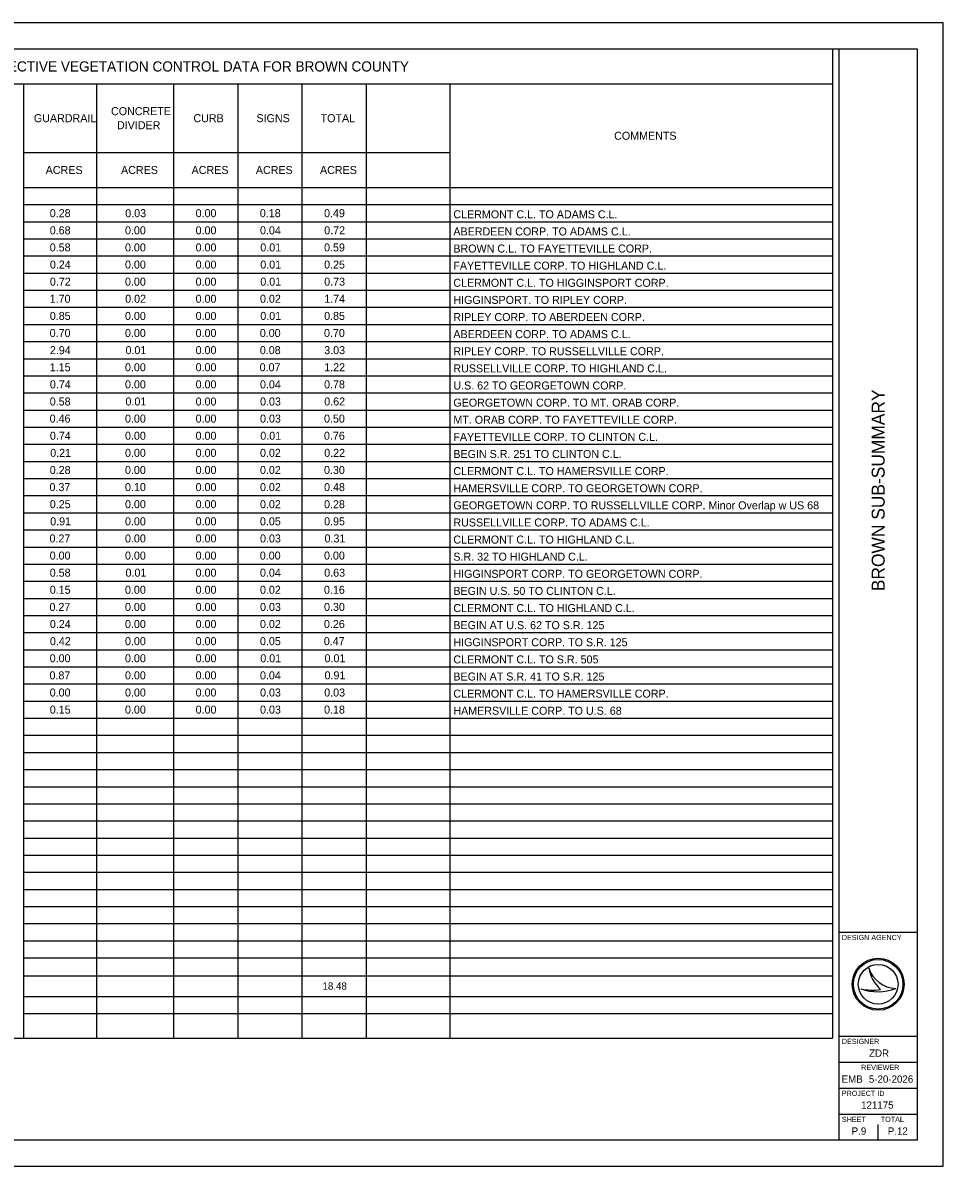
# Model space of a CAD drawing. Extents: x 0 to 34, y 0 to 22.
# Drawn here: x 16.29 to 34, y 0 to 22 of the extents above; entities that cross this region are included whole.
import ezdxf

# ---------------------------------------------------------------- set-up
doc = ezdxf.new("R2010")
doc.units = 0
for name, color, linetype in [('SH_Border', 7, 'Continuous'), ('SH_Cut_Line', 7, 'Continuous'), ('SH_Data', 7, 'Continuous'), ('SH_Text', 7, 'Continuous')]:
    doc.layers.add(name, color=color, linetype=linetype)

msp = doc.modelspace()

# ---------------------------------------------------------------- linework, layer by layer
at = {"layer": 'SH_Border'}
for p, q in [((32, 0.5), (32, 21.5)), ((32, 4.5), (33.5, 4.5)), ((32, 2.5), (33.5, 2.5)), ((32, 2), (33.5, 2)), ((32, 1.5), (33.5, 1.5)), ((32, 1), (33.5, 1))]:
    msp.add_line(p, q, dxfattribs=at)
msp.add_lwpolyline([(1.5, 21.5), (33.5, 21.5), (33.5, 0.5), (1.5, 0.5)], close=True, dxfattribs=at)
at = {"layer": 'SH_Cut_Line'}
msp.add_lwpolyline([(0, 0), (34, 0), (34, 22), (0, 22)], close=True, dxfattribs=at)
at = {"layer": 'SH_Data'}
for p, q in [((32.567, 3.81), (32.567, 3.81)), ((32.417, 3.41), (32.417, 3.41)), ((32.75, 3.5), (32.75, 3.5)), ((33.087, 3.419), (33.087, 3.419)), ((32.375, 0.675), (32.375, 0.675)), ((32.75, 0.5), (32.75, 0.8))]:
    msp.add_line(p, q, dxfattribs=at)
for radius in [0.5, 0.477, 0.477, 0.382]:
    msp.add_circle((32.75, 3.5), radius, dxfattribs=at)
for centre, radius, start, end in [((33.116, 3.998), 0.58, 198.9257, 198.9319), ((33.347, 3.97), 0.796, 191.6379, 191.6421), ((33.116, 3.998), 0.58, 198.9319, 267.1657), ((33.347, 3.97), 0.796, 191.6421, 226.0947), ((32.739, 4.37), 1.013, 251.4576, 290.0832), ((32.648, 4.654), 1.266, 259.4964, 259.4995), ((32.739, 4.37), 1.013, 251.4527, 251.4576), ((32.648, 4.654), 1.266, 259.4995, 276.6672)]:
    msp.add_arc(centre, radius, start, end, dxfattribs=at)
at = {"layer": 'SH_Text'}
for p, q in [((1.5, 21.5), (31.872, 21.5)), ((31.872, 21.5), (31.872, 2.46)), ((7.451, 20.825), (16.302, 20.825)), ((16.28, 20.825), (31.872, 20.825)), ((16.302, 20.825), (16.302, 2.46)), ((17.707, 20.825), (17.707, 2.46)), ((19.189, 20.825), (19.189, 2.46)), ((20.425, 20.825), (20.425, 2.46)), ((21.66, 20.825), (21.66, 2.46)), ((22.895, 20.825), (22.895, 2.46)), ((24.509, 20.825), (24.509, 2.46)), ((16.302, 19.507), (24.509, 19.507)), ((16.302, 18.832), (31.872, 18.832)), ((16.302, 18.502), (31.872, 18.502)), ((16.302, 18.173), (31.872, 18.173)), ((16.302, 17.844), (31.872, 17.844)), ((16.302, 17.514), (31.872, 17.514)), ((16.302, 17.185), (31.872, 17.185)), ((16.302, 16.855), (31.872, 16.855)), ((16.302, 16.526), (31.872, 16.526)), ((16.302, 16.196), (31.872, 16.196)), ((16.302, 15.867), (31.872, 15.867)), ((16.302, 15.538), (31.872, 15.538)), ((16.302, 15.208), (31.872, 15.208)), ((16.302, 14.879), (31.872, 14.879)), ((16.302, 14.549), (31.872, 14.549)), ((16.302, 14.22), (31.872, 14.22)), ((16.302, 13.891), (31.872, 13.891)), ((16.302, 13.561), (31.872, 13.561)), ((16.302, 13.232), (31.872, 13.232)), ((16.302, 12.902), (31.872, 12.902)), ((16.302, 12.573), (31.872, 12.573)), ((16.302, 12.244), (31.872, 12.244)), ((16.302, 11.914), (31.872, 11.914)), ((16.302, 11.585), (31.872, 11.585)), ((16.302, 11.255), (31.872, 11.255)), ((16.302, 10.926), (31.872, 10.926)), ((16.302, 10.596), (31.872, 10.596)), ((16.302, 10.267), (31.872, 10.267)), ((16.302, 9.938), (31.872, 9.938)), ((16.302, 9.608), (31.872, 9.608)), ((16.302, 9.279), (31.872, 9.279)), ((16.302, 8.949), (31.872, 8.949)), ((16.302, 8.62), (31.872, 8.62)), ((16.302, 8.291), (31.872, 8.291)), ((16.302, 7.961), (31.872, 7.961)), ((16.302, 7.632), (31.872, 7.632)), ((16.302, 7.302), (31.872, 7.302)), ((16.302, 6.973), (31.872, 6.973)), ((16.302, 6.644), (31.872, 6.644)), ((16.302, 6.314), (31.872, 6.314)), ((16.302, 5.985), (31.872, 5.985)), ((16.302, 5.655), (31.872, 5.655)), ((16.302, 5.326), (31.872, 5.326)), ((16.302, 4.996), (31.872, 4.996)), ((16.302, 4.667), (31.872, 4.667)), ((16.302, 4.338), (31.872, 4.338)), ((16.302, 4.008), (31.872, 4.008)), ((16.302, 3.662), (31.872, 3.662)), ((16.302, 3.267), (31.872, 3.267)), ((16.302, 2.938), (31.872, 2.938)), ((7.451, 2.46), (16.302, 2.46)), ((16.28, 2.46), (31.872, 2.46))]:
    msp.add_line(p, q, dxfattribs=at)

# ---------------------------------------------------------------- texts
at = {"layer": 'SH_Data'}
msp.add_text('BROWN SUB-SUMMARY', height=0.25, rotation=90, dxfattribs=at).set_placement((32.875, 11.064))
for s, height, p in [('DESIGN AGENCY', 0.1, (32.05, 4.35)), ('DESIGNER', 0.1, (32.05, 2.35)), ('ZDR', 0.14, (32.575, 2.105)), ('REVIEWER', 0.1, (32.422, 1.85)), ('EMB', 0.14, (32.047, 1.605)), ('5-20-2026', 0.14, (32.571, 1.605)), ('PROJECT ID', 0.1, (32.05, 1.35)), ('121175', 0.14, (32.421, 1.105)), ('SHEET', 0.1, (32.05, 0.85)), ('TOTAL', 0.1, (32.8, 0.85)), ('P.9', 0.14, (32.24, 0.605)), ('P.12', 0.14, (32.935, 0.605))]:
    msp.add_text(s, height=height, dxfattribs=at).set_placement(p)
at = {"layer": 'SH_Text'}
for s, height, p in [('HERBICIDAL SPRAYING NONSELECTIVE VEGETATION CONTROL DATA FOR BROWN COUNTY', 0.196, (11.852, 21.064)), ('GUARDRAIL', 0.154, (16.503, 20.089)), ('CONCRETE', 0.154, (17.987, 20.224)), ('CURB', 0.154, (19.573, 20.089)), ('SIGNS', 0.154, (20.786, 20.089)), ('TOTAL', 0.154, (22.02, 20.089)), ('DIVIDER', 0.154, (18.102, 19.954)), ('COMMENTS', 0.154, (27.669, 19.751)), ('ACRES', 0.154, (16.73, 19.092)), ('ACRES', 0.154, (18.18, 19.092)), ('ACRES', 0.154, (19.538, 19.092)), ('ACRES', 0.154, (20.774, 19.092)), ('ACRES', 0.154, (22.009, 19.092)), ('0.28', 0.154, (16.808, 18.261)), ('0.03', 0.154, (18.261, 18.261)), ('0.00', 0.154, (19.615, 18.261)), ('0.18', 0.154, (20.851, 18.261)), ('0.49', 0.154, (22.087, 18.261)), ('CLERMONT C.L. TO ADAMS C.L.', 0.154, (24.575, 18.239)), ('0.68', 0.154, (16.808, 17.931)), ('0.00', 0.154, (18.256, 17.931)), ('0.00', 0.154, (19.615, 17.931)), ('0.04', 0.154, (20.854, 17.931)), ('0.72', 0.154, (22.09, 17.931)), ('ABERDEEN CORP. TO ADAMS C.L.', 0.154, (24.575, 17.909)), ('0.58', 0.154, (16.808, 17.602)), ('0.00', 0.154, (18.256, 17.602)), ('0.00', 0.154, (19.615, 17.602)), ('0.01', 0.154, (20.86, 17.602)), ('0.59', 0.154, (22.087, 17.602)), ('BROWN C.L. TO FAYETTEVILLE CORP.', 0.154, (24.575, 17.58)), ('0.24', 0.154, (16.811, 17.272)), ('0.00', 0.154, (18.256, 17.272)), ('0.00', 0.154, (19.615, 17.272)), ('0.01', 0.154, (20.86, 17.272)), ('0.25', 0.154, (22.088, 17.272)), ('FAYETTEVILLE CORP. TO HIGHLAND C.L.', 0.154, (24.575, 17.251)), ('0.72', 0.154, (16.811, 16.943)), ('0.00', 0.154, (18.256, 16.943)), ('0.00', 0.154, (19.615, 16.943)), ('0.01', 0.154, (20.86, 16.943)), ('0.73', 0.154, (22.09, 16.943)), ('CLERMONT C.L. TO HIGGINSPORT CORP.', 0.154, (24.575, 16.921)), ('1.70', 0.154, (16.807, 16.614)), ('0.02', 0.154, (18.26, 16.614)), ('0.00', 0.154, (19.615, 16.614)), ('0.02', 0.154, (20.854, 16.614)), ('1.74', 0.154, (22.09, 16.614)), ('HIGGINSPORT. TO RIPLEY CORP.', 0.154, (24.575, 16.592)), ('0.85', 0.154, (16.809, 16.284)), ('0.00', 0.154, (18.256, 16.284)), ('0.00', 0.154, (19.615, 16.284)), ('0.01', 0.154, (20.86, 16.284)), ('0.85', 0.154, (22.088, 16.284)), ('RIPLEY CORP. TO ABERDEEN CORP.', 0.154, (24.575, 16.262)), ('0.70', 0.154, (16.807, 15.955)), ('0.00', 0.154, (18.256, 15.955)), ('0.00', 0.154, (19.615, 15.955)), ('0.00', 0.154, (20.85, 15.955)), ('0.70', 0.154, (22.086, 15.955)), ('ABERDEEN CORP. TO ADAMS C.L.', 0.154, (24.575, 15.933)), ('2.94', 0.154, (16.811, 15.625)), ('0.01', 0.154, (18.266, 15.625)), ('0.00', 0.154, (19.615, 15.625)), ('0.08', 0.154, (20.851, 15.625)), ('3.03', 0.154, (22.09, 15.625)), ('RIPLEY CORP. TO RUSSELLVILLE CORP.', 0.154, (24.575, 15.604)), ('1.15', 0.154, (16.809, 15.296)), ('0.00', 0.154, (18.256, 15.296)), ('0.00', 0.154, (19.615, 15.296)), ('0.07', 0.154, (20.847, 15.296)), ('1.22', 0.154, (22.09, 15.296)), ('RUSSELLVILLE CORP. TO HIGHLAND C.L.', 0.154, (24.575, 15.274)), ('0.74', 0.154, (16.811, 14.967)), ('0.00', 0.154, (18.256, 14.967)), ('0.00', 0.154, (19.615, 14.967)), ('0.04', 0.154, (20.854, 14.967)), ('0.78', 0.154, (22.087, 14.967)), ('U.S. 62 TO GEORGETOWN CORP.', 0.154, (24.575, 14.945)), ('0.58', 0.154, (16.808, 14.637)), ('0.01', 0.154, (18.266, 14.637)), ('0.00', 0.154, (19.615, 14.637)), ('0.03', 0.154, (20.855, 14.637)), ('0.62', 0.154, (22.09, 14.637)), ('GEORGETOWN CORP. TO MT. ORAB CORP.', 0.154, (24.575, 14.615)), ('0.46', 0.154, (16.806, 14.308)), ('0.00', 0.154, (18.256, 14.308)), ('0.00', 0.154, (19.615, 14.308)), ('0.03', 0.154, (20.855, 14.308)), ('0.50', 0.154, (22.086, 14.308)), ('MT. ORAB CORP. TO FAYETTEVILLE CORP.', 0.154, (24.575, 14.286)), ('0.74', 0.154, (16.811, 13.978)), ('0.00', 0.154, (18.256, 13.978)), ('0.00', 0.154, (19.615, 13.978)), ('0.01', 0.154, (20.86, 13.978)), ('0.76', 0.154, (22.085, 13.978)), ('FAYETTEVILLE CORP. TO CLINTON C.L.', 0.154, (24.575, 13.956)), ('0.21', 0.154, (16.817, 13.649)), ('0.00', 0.154, (18.256, 13.649)), ('0.00', 0.154, (19.615, 13.649)), ('0.02', 0.154, (20.854, 13.649)), ('0.22', 0.154, (22.09, 13.649)), ('BEGIN S.R. 251 TO CLINTON C.L.', 0.154, (24.575, 13.627)), ('0.28', 0.154, (16.808, 13.319)), ('0.00', 0.154, (18.256, 13.319)), ('0.00', 0.154, (19.615, 13.319)), ('0.02', 0.154, (20.854, 13.319)), ('0.30', 0.154, (22.086, 13.319)), ('CLERMONT C.L. TO HAMERSVILLE CORP.', 0.154, (24.575, 13.298)), ('0.37', 0.154, (16.803, 12.99)), ('0.10', 0.154, (18.256, 12.99)), ('0.00', 0.154, (19.615, 12.99)), ('0.02', 0.154, (20.854, 12.99)), ('0.48', 0.154, (22.087, 12.99)), ('HAMERSVILLE CORP. TO GEORGETOWN CORP.', 0.154, (24.575, 12.968)), ('0.25', 0.154, (16.809, 12.661)), ('0.00', 0.154, (18.256, 12.661)), ('0.00', 0.154, (19.615, 12.661)), ('0.02', 0.154, (20.854, 12.661)), ('0.28', 0.154, (22.087, 12.661)), ('GEORGETOWN CORP. TO RUSSELLVILLE CORP. Minor Overlap w US 68', 0.154, (24.575, 12.639)), ('0.91', 0.154, (16.817, 12.331)), ('0.00', 0.154, (18.256, 12.331)), ('0.00', 0.154, (19.615, 12.331)), ('0.05', 0.154, (20.853, 12.331)), ('0.95', 0.154, (22.088, 12.331)), ('RUSSELLVILLE CORP. TO ADAMS C.L.', 0.154, (24.575, 12.309)), ('0.27', 0.154, (16.803, 12.002)), ('0.00', 0.154, (18.256, 12.002)), ('0.00', 0.154, (19.615, 12.002)), ('0.03', 0.154, (20.855, 12.002)), ('0.31', 0.154, (22.096, 12.002)), ('CLERMONT C.L. TO HIGHLAND C.L.', 0.154, (24.575, 11.98)), ('0.00', 0.154, (16.807, 11.672)), ('0.00', 0.154, (18.256, 11.672)), ('0.00', 0.154, (19.615, 11.672)), ('0.00', 0.154, (20.85, 11.672)), ('0.00', 0.154, (22.086, 11.672)), ('S.R. 32 TO HIGHLAND C.L.', 0.154, (24.575, 11.651)), ('0.58', 0.154, (16.808, 11.343)), ('0.01', 0.154, (18.266, 11.343)), ('0.00', 0.154, (19.615, 11.343)), ('0.04', 0.154, (20.854, 11.343)), ('0.63', 0.154, (22.09, 11.343)), ('HIGGINSPORT CORP. TO GEORGETOWN CORP.', 0.154, (24.575, 11.321)), ('0.15', 0.154, (16.809, 11.014)), ('0.00', 0.154, (18.256, 11.014)), ('0.00', 0.154, (19.615, 11.014)), ('0.02', 0.154, (20.854, 11.014)), ('0.16', 0.154, (22.085, 11.014)), ('BEGIN U.S. 50 TO CLINTON C.L.', 0.154, (24.575, 10.992)), ('0.27', 0.154, (16.803, 10.684)), ('0.00', 0.154, (18.256, 10.684)), ('0.00', 0.154, (19.615, 10.684)), ('0.03', 0.154, (20.855, 10.684)), ('0.30', 0.154, (22.086, 10.684)), ('CLERMONT C.L. TO HIGHLAND C.L.', 0.154, (24.575, 10.662)), ('0.24', 0.154, (16.811, 10.355)), ('0.00', 0.154, (18.256, 10.355)), ('0.00', 0.154, (19.615, 10.355)), ('0.02', 0.154, (20.854, 10.355)), ('0.26', 0.154, (22.085, 10.355)), ('BEGIN AT U.S. 62 TO S.R. 125', 0.154, (24.575, 10.333)), ('0.42', 0.154, (16.811, 10.025)), ('0.00', 0.154, (18.256, 10.025)), ('0.00', 0.154, (19.615, 10.025)), ('0.05', 0.154, (20.853, 10.025)), ('0.47', 0.154, (22.082, 10.025)), ('HIGGINSPORT CORP. TO S.R. 125', 0.154, (24.575, 10.004)), ('0.00', 0.154, (16.807, 9.696)), ('0.00', 0.154, (18.256, 9.696)), ('0.00', 0.154, (19.615, 9.696)), ('0.01', 0.154, (20.86, 9.696)), ('0.01', 0.154, (22.096, 9.696)), ('CLERMONT C.L. TO S.R. 505', 0.154, (24.575, 9.674)), ('0.87', 0.154, (16.803, 9.367)), ('0.00', 0.154, (18.256, 9.367)), ('0.00', 0.154, (19.615, 9.367)), ('0.04', 0.154, (20.854, 9.367)), ('0.91', 0.154, (22.096, 9.367)), ('BEGIN AT S.R. 41 TO S.R. 125', 0.154, (24.575, 9.345)), ('0.00', 0.154, (16.807, 9.037)), ('0.00', 0.154, (18.256, 9.037)), ('0.00', 0.154, (19.615, 9.037)), ('0.03', 0.154, (20.855, 9.037)), ('0.03', 0.154, (22.09, 9.037)), ('CLERMONT C.L. TO HAMERSVILLE CORP.', 0.154, (24.575, 9.015)), ('0.15', 0.154, (16.809, 8.708)), ('0.00', 0.154, (18.256, 8.708)), ('0.00', 0.154, (19.615, 8.708)), ('0.03', 0.154, (20.855, 8.708)), ('0.18', 0.154, (22.087, 8.708)), ('HAMERSVILLE CORP. TO U.S. 68', 0.154, (24.575, 8.686)), ('18.48', 0.14, (22.057, 3.395))]:
    msp.add_text(s, height=height, dxfattribs=at).set_placement(p)

doc.saveas('drawing.dxf')
